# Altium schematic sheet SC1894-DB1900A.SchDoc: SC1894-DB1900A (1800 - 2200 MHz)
size B; Organization: Maxim Integrated; Address1: 160 Rio Robles; Address2: San Jose, CA. 95134; Address3: U.S.A.; Address4: 408-601-1000; Revision: 2.0; SheetNumber: 1; SheetTotal: 1; PageSetup: Record=PageOptions¦CenterHorizontal=True¦CenterVertical=True¦PrintScale=1.12¦XCorrection=1.00¦YCorrection=1.00¦PrintKind=1¦BorderSize=5000000¦LeftOffset=0¦BottomOffset=0¦Orientation=2¦PaperLength=1000¦PaperWidth=1000¦Scale=100¦PaperSource=15¦PrintQuality=600¦MediaType=1¦DitherType=10¦PaperKind=Tabloid¦PrintScaleMode=1
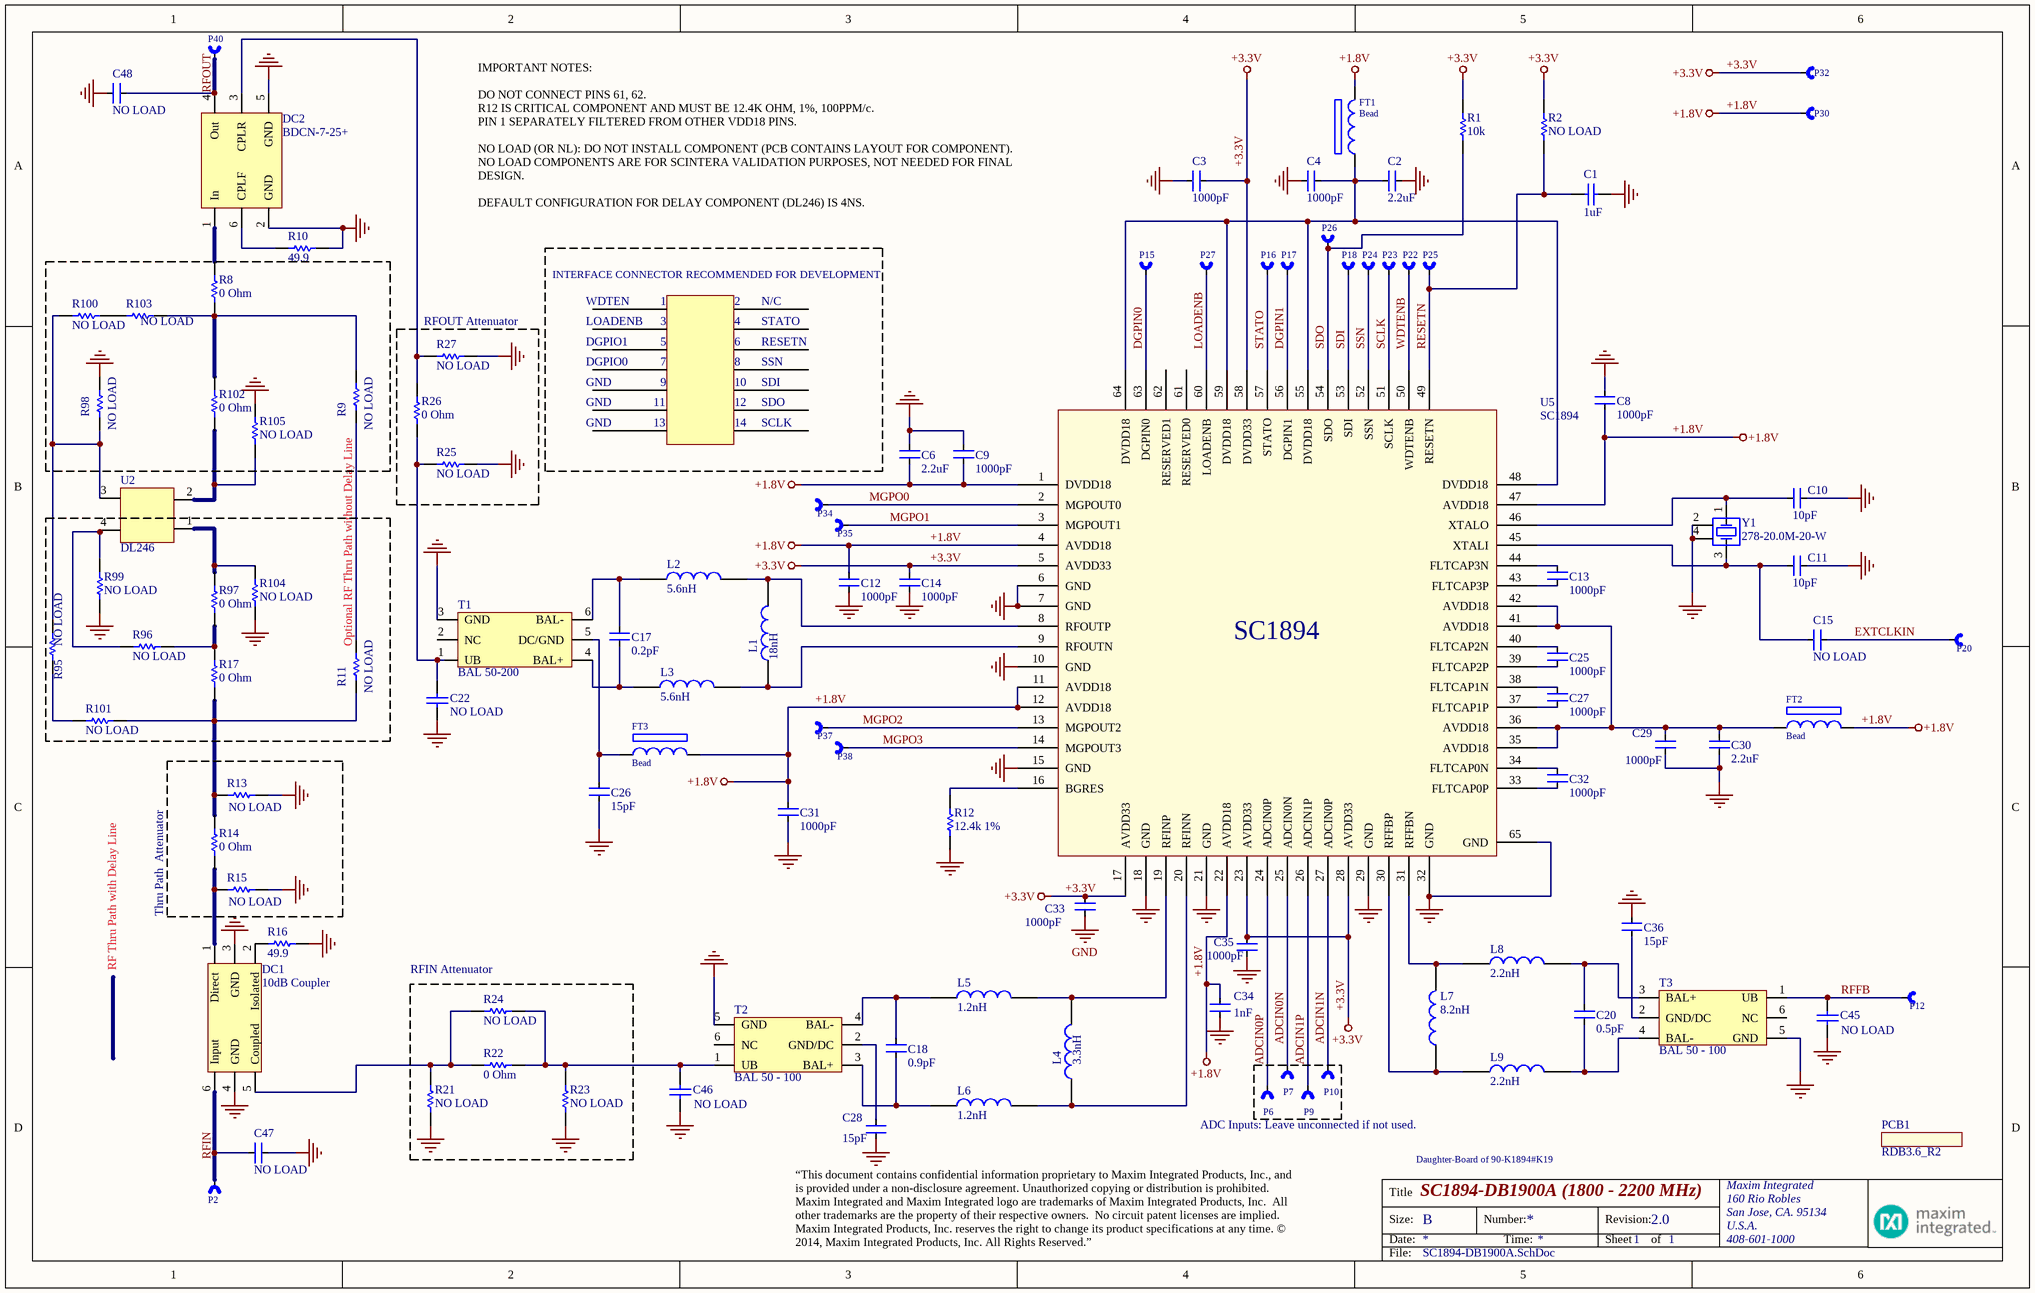
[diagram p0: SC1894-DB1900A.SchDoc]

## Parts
C1  1uF  [1608[0603]]
C2  2.2uF  [0603 SMD]
C3  1000pF  [0402 SMD]
C4  1000pF  [0402 SMD]
C6  2.2uF  [0603 SMD]
C8  1000pF  [0402 SMD]
C9  1000pF  [0402 SMD]
C10  10pF  [0402 SMD]
C11  10pF  [0402 SMD]
C12  1000pF  [0402 SMD]
C13  1000pF  [0402 SMD]
C14  1000pF  [0402 SMD]
C15  NO LOAD  [0402 SMD]
C17  0.2pF  [0402 SMD]
C18  0.9pF  [0402 SMD]
C20  0.5pF  [0402 SMD]
C22  NO LOAD  [0402 SMD]
C25  1000pF  [0402 SMD]
C26  15pF  [0402 SMD]
C27  1000pF  [0402 SMD]
C28  15pF  [0402 SMD]
C29  1000pF  [0402 SMD]
C30  2.2uF  [0603 SMD]
C31  1000pF  [0402 SMD]
C32  1000pF  [0402 SMD]
C33  1000pF  [0402 SMD]
C34  1nF  [0402 SMD]
C35  1000pF  [0402 SMD]
C36  15pF  [0402 SMD]
C45  NO LOAD  [0402 SMD]
C46  NO LOAD  [0402 SMD]
C47  NO LOAD  [0402 SMD]
C48  NO LOAD  [0402 SMD]
DC1  10dB Coupler  [0805 COUPLER ANAREN]
DC2  BDCN-7-25+  [BDCN-7-25+]
FT1  Bead  [0603 SMD]
FT2  Bead  [0603 SMD]
FT3  Bead  [0402 SMD]
L1  18nH  [0402 SMD]
L2  5.6nH  [0402 SMD]
L3  5.6nH  [0402 SMD]
L4  3.3nH  [0402 SMD]
L5  1.2nH  [0402 SMD]
L6  1.2nH  [0402 SMD]
L7  8.2nH  [0402 SMD]
L8  2.2nH  [0402 SMD]
L9  2.2nH  [0402 SMD]
P2  PORT 1-M  [PORT-1_M-PAD]  (value not drawn)
P6  PORT 1-M  [PORT-1_M-PAD]  (value not drawn)
P7  PORT 1-M  [PORT-1_M-PAD]  (value not drawn)
P9  PORT 1-M  [PORT-1_M-PAD]  (value not drawn)
P10  PORT 1-M  [PORT-1_M-PAD]  (value not drawn)
P12  PORT 1-M  [PORT-1_M-PAD]  (value not drawn)
P15  PORT 1-M  [PORT-1_M-PAD]  (value not drawn)
P16  PORT 1-M  [PORT-1_M-PAD]  (value not drawn)
P17  PORT 1-M  [PORT-1_M-PAD]  (value not drawn)
P18  PORT 1-M  [PORT-1_M-PAD]  (value not drawn)
P20  PORT 1-M  [PORT-1_M-PAD]  (value not drawn)
P22  PORT 1-M  [PORT-1_M-PAD]  (value not drawn)
P23  PORT 1-M  [PORT-1_M-PAD]  (value not drawn)
P24  PORT 1-M  [PORT-1_M-PAD]  (value not drawn)
P25  PORT 1-M  [PORT-1_M-PAD]  (value not drawn)
P26  PORT 1-M  [PORT-1_M-PAD]  (value not drawn)
P27  PORT 1-M  [PORT-1_M-PAD]  (value not drawn)
P30  PORT 1-M  [PORT-1_M-PAD]  (value not drawn)
P32  PORT 1-M  [PORT-1_M-PAD]  (value not drawn)
P34  PORT 1-M  [PORT-1_M-PAD]  (value not drawn)
P35  PORT 1-M  [PORT-1_M-PAD]  (value not drawn)
P37  PORT 1-M  [PORT-1_M-PAD]  (value not drawn)
P38  PORT 1-M  [PORT-1_M-PAD]  (value not drawn)
P40  PORT 1-M  [PORT-1_M-PAD]  (value not drawn)
PCB1  RDB3.6_R2
R1  10k  [0402 SMD]
R2  NO LOAD  [0402 SMD]
R8  0 Ohm  [0402 SMD]
R9  NO LOAD  [0402 SMD]
R10  49.9  [0402 SMD]
R11  NO LOAD  [0402 SMD]
R12  12.4k 1%  [0402 SMD]
R13  NO LOAD  [0402 SMD]
R14  0 Ohm  [0402 SMD]
R15  NO LOAD  [0402 SMD]
R16  49.9  [0402 SMD]
R17  0 Ohm  [0402 SMD]
R21  NO LOAD  [0402 SMD]
R22  0 Ohm  [0201_SMT]
R23  NO LOAD  [0402 SMD]
R24  NO LOAD  [0201_SMT]
R25  NO LOAD  [0402 SMD]
R26  0 Ohm  [0402 SMD]
R27  NO LOAD  [0402 SMD]
R95  NO LOAD  [0402 SMD]
R96  NO LOAD  [0402 SMD]
R97  0 Ohm  [0402 SMD]
R98  NO LOAD  [0402 SMD]
R99  NO LOAD  [0402 SMD]
R100  NO LOAD  [0402 SMD]
R101  NO LOAD  [0402 SMD]
R102  0 Ohm  [0402 SMD]
R103  NO LOAD  [0402 SMD]
R104  NO LOAD  [0402 SMD]
R105  NO LOAD  [0402 SMD]
T1  BAL 50-200
T2  BAL 50 - 100  [0805 BALUN Anaren]
T3  BAL 50 - 100  [0805 BALUN Anaren]
U2  DL246  [DL246-A]
U5  SC1894  [SC1894]
Y1  278-20.0M-20-W  [278-20.0M]

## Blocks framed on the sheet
RFOUT Attenuator: R25-R27
Optional RF Thru Path without Delay Line: R11 R17 R95-R97 R99 R101 R104
Thru Path  Attenuator: R13-R15
RFIN Attenuator: R21-R24

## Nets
+1.8V: C6.2 C8.2 C9.2 C12.1 C31.2 C34.2 FT1.2 FT2.2 FT3.2 P30.1(P*) U5.1(DVDD18) U5.4(AVDD18) U5.11(AVDD18) U5.12(AVDD18) U5.22(AVDD18) U5.47(AVDD18)
+3.3V: C3.2 C14.1 C33.1 C35.2 P32.1(P*) R1.1 R2.2 U5.5(AVDD33) U5.17(AVDD33) U5.23(AVDD33) U5.28(AVDD33) U5.58(DVDD33)
GND: C1.1 C2.2 C3.1 C4.1 C6.1 C8.1 C9.1 C10.2 C11.2 C12.2 C14.2 C22.1 C26.2 C28.2 C29.2 C30.2 C31.1 C33.2 C34.1 C35.1 C36.2 C45.1 C46.1 C47.2 C48.1 DC1.3(GND) DC1.4(GND) DC2.2(GND) DC2.5(GND) R10.2 R12.2 R13.2 R15.2 R16.2 R21.2 R23.2 R25.1 R27.1 R98.1 R99.1 R104.1 R105.2 T1.3(GND) T2.5(GND) T3.5(GND) U5.6(GND) U5.7(GND) U5.10(GND) U5.15(GND) U5.18(GND) U5.21(GND) U5.29(GND) U5.32(GND) U5.65(GND) Y1.2(SHIELD1) Y1.4(SHIELD2)
ADCIN0N: P7.1(P*) U5.25(ADCIN0N)
ADCIN0P: P6.1(P*) U5.24(ADCIN0P)
ADCIN1N: P10.1(P*) U5.27(ADCIN0P)
ADCIN1P: P9.1(P*) U5.26(ADCIN1P)
DGPIN0: P15.1(P*) U5.63(DGPIN0)
DGPIN1: P17.1(P*) U5.56(DGPIN1)
EXTCLKIN: C15.2 P20.1(P*)
LOADENB: P27.1(P*) U5.60(LOADENB)
MGPO0: P34.1(P*) U5.2(MGPOUT0)
MGPO1: P35.1(P*) U5.3(MGPOUT1)
MGPO2: P37.1(P*) U5.13(MGPOUT2)
MGPO3: P38.1(P*) U5.14(MGPOUT3)
RESETN: C1.2 P25.1(P*) R2.1 U5.49(RESETN)
RFFB: C45.2 P12.1(P*) T3.1(UB)
RFIN: C47.1 DC1.6(Input) P2.1(P*)
RFOUT: C48.2 DC2.4(Out) P40.1(P*)
SCLK: P23.1(P*) U5.51(SCLK)
SDI: P18.1(P*) U5.53(SDI)
SDO: P26.1(P*) R1.2 U5.54(SDO)
SSN: P24.1(P*) U5.52(SSN)
STATO: P16.1(P*) U5.57(STATO)
WDTENB: P22.1(P*) U5.50(WDTENB)
NetC2_1: C2.1 C4.2 FT1.1 U5.48(DVDD18) U5.55(DVDD18) U5.59(DVDD18) U5.64(DVDD18)
NetC10_1: C10.1 U5.46(XTALO) Y1.1(OSC1)
NetC11_1: C11.1 C15.1 U5.45(XTALI) Y1.3(OSC2)
NetC13_1: C13.1 U5.44(FLTCAP3N)
NetC13_2: C13.2 U5.43(FLTCAP3P)
NetC17_1: C17.1 L2.1 T1.6(BAL-)
NetC17_2: C17.2 L3.1 T1.4(BAL+)
NetC18_1: C18.1 L5.1 T2.4(BAL-)
NetC18_2: C18.2 L6.1 T2.3(BAL+)
NetC20_1: C20.1 L8.2 T3.3(BAL+)
NetC20_2: C20.2 L9.2 T3.4(BAL-)
NetC22_2: C22.2 R25.2 R26.1 T1.1(UB)
NetC25_1: C25.1 U5.40(FLTCAP2N)
NetC25_2: C25.2 U5.39(FLTCAP2P)
NetC26_1: C26.1 FT3.1 T1.5(DC/GND)
NetC27_1: C27.1 U5.38(FLTCAP1N)
NetC27_2: C27.2 U5.37(FLTCAP1P)
NetC28_1: C28.1 T2.2(GND/DC)
NetC29_1: C29.1 C30.1 FT2.1 U5.35(AVDD18) U5.36(AVDD18) U5.41(AVDD18) U5.42(AVDD18)
NetC32_1: C32.1 U5.34(FLTCAP0N)
NetC32_2: C32.2 U5.33(FLTCAP0P)
NetC36_1: C36.1 T3.2(GND/DC)
NetC46_2: C46.2 R22.2 R23.1 R24.2 T2.1(UB)
NetDC1_1: DC1.1(Direct) R14.1 R15.1
NetDC1_2: DC1.2(Isolated) R16.1
NetDC1_5: DC1.5(Coupled) R21.1 R22.1 R24.1
NetDC2_1: DC2.1(In) R8.2
NetDC2_3: DC2.3(CPLR) R26.2 R27.2
NetDC2_6: DC2.6(CPLF) R10.1
NetL1_1: L1.1 L3.2 U5.9(RFOUTN)
NetL1_2: L1.2 L2.2 U5.8(RFOUTP)
NetL4_1: L4.1 L6.2 U5.20(RFINN)
NetL4_2: L4.2 L5.2 U5.19(RFINP)
NetL7_1: L7.1 L9.1 U5.30(RFFBP)
NetL7_2: L7.2 L8.1 U5.31(RFFBN)
NetR8_1: R8.1 R9.2 R102.2 R103.2
NetR9_1: R9.1 R11.2
NetR11_1: R11.1 R13.1 R14.2 R17.1 R101.2
NetR12_1: R12.1 U5.16(BGRES)
NetR17_2: R17.2 R96.2 R97.1
NetR95_1: R95.1 R101.1
NetR95_2: R95.2 R98.2 R100.1 U2.3(2ns_B)
NetR96_1: R96.1 R99.2 U2.4(2ns_A)
NetR97_2: R97.2 R104.2 U2.1(4ns_A)
NetR100_2: R100.2 R103.1
NetR102_1: R102.1 R105.1 U2.2(4ns_B)

Not connected (* = marked no-connect by the designer): T1 2(NC); T2 6(NC); T3 6(NC); U5 61(RESERVED0) 62(RESERVED1)

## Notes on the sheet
- IMPORTANT NOTES:
  DO NOT CONNECT PINS 61, 62.
  R12 IS CRITICAL COMPONENT AND MUST BE 12.4K OHM, 1%, 100PPM/c.
  PIN 1 SEPARATELY FILTERED FROM OTHER VDD18 PINS.
  NO LOAD (OR NL): DO NOT INSTALL COMPONENT (PCB CONTAINS LAYOUT FOR COMPONENT).
  NO LOAD COMPONENTS ARE FOR SCINTERA VALIDATION PURPOSES, NOT NEEDED FOR FINAL DESIGN.
  DEFAULT CONFIGURATION FOR DELAY COMPONENT (DL246) IS 4NS.
- INTERFACE CONNECTOR RECOMMENDED FOR DEVELOPMENT
- WDTEN
- LOADENB
- DGPIO1
- DGPIO0
- 1
- 3
- 5
- 7
- 2
- 4
- 6
- 8
- N/C
- STATO
- RESETN
- SSN
- GND
- 11
- 13
- 9
- 10
- 12
- 14
- SDI
- SDO
- SCLK
- RF Thru Path with Delay Line
- ADC Inputs: Leave unconnected if not used.
- Daughter-Board of 90-K1894#K19
- (near C28) “This document contains confidential information proprietary to Maxim Integrated Products, Inc., and is provided under a non-disclosure agreement. Unauthorized copying or distribution is prohibited.  Maxim Integrated and Maxim Integrated logo are trademarks of Maxim Integrated Products, Inc.  All other trademarks are the property of their respective owners.  No circuit patent licenses are implied.  Maxim Integrated Products, Inc. reserves the right to change its product specifications at any time. © 2014, Maxim Integrated Products, Inc. All Rights Reserved.”

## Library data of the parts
C1 = 1u: 1uF 0603 ceramic capacitor
C2 C6 C30 = Cap 2.2uF 0603: 2.2uF 0603
C3 C4 C8 C9 C12-C14 C25 C27 C29 C31-C35 = Cap 1000pF: 1000pF 0402
C10 C11 C15 = Cap 10pF: 10pF 0402
C17 = Cap 0.2pF: 0.2pF 0402; Part Substitution Allowed?: No
C18 = Cap 0.9pF: 0.9pF 0402; Part Substitution Allowed?: No
C20 = Cap 0.5pF: 0.5pF 0402; Part Substitution Allowed?: No
C22 C45 C46 = Capacitor: Generic Capacitor
C26 C28 C36 = Cap 15pF: 15pF 0402
C47 C48 = Cap No Load 0402: 0402 Cap No Load
DC1 = DC1722J5010AHF: Anaren 1700 - 2200 MHz 0805 10dB Coupler; Part Substitution Allowed?: No
DC2 = BDCN-7-25+: Mini Circuits Balun; Manufacturer 1: Mini-Circuits; Part Substitution Allowed?: No
FT1 FT2 = Bead 0603: Part Substitution Allowed?: No; Value: 120mH
FT3 = Bead 0402: Bead 0402 470 ohm; Part Substitution Allowed?: No; Value: 470mH
L1 = 18nH: Part Substitution Allowed?: No
L2 L3 = 5.6nH: Part Substitution Allowed?: No
L5 L6 = 1.2nH: Part Substitution Allowed?: No
L7 = 8.2nH: Part Substitution Allowed?: No
L8 L9 = 2.2nH: Part Substitution Allowed?: No
P2 P6 P7 P9 P10 P12 P15-P18 P20 P22-P27 P30 P32 P34 P35 P37 P38 P40 = PORT 1-M: Ports of RDB Daughterboards
PCB1 = RDB3.6_R2: Printed Circuit Board (RDB3.6_R2)
R1 = 10k Ohm 0402
R2 R21 R23 R95 R96 R99-R101 R103-R105 = RES NL 0402: NO LOAD RESISTOR 0402
R8 R14 R17 R26 R97 R102 = 0 Ohm 0402
R9 R11 R13 R15 R25 R27 R98 = Resistor: Resistor Generic
R10 R16 = 49.9 Ohm: 40 Ohm 0402
R12 = 12.4k Ohm 0402
R22 = 0 Ohm 0201
R24 = RES NL 0201: NO LOAD RESISTOR 0201
T1 = DXP18BN5014T
T2 T3 = BD1722J50100A00: Anaren 1700 - 2200 MHz 50Ohm UnBal - 100 Dif Balun; Part Substitution Allowed?: No
U2 = DL246: Kyocera Delay Line DL246; Part Substitution Allowed?: No
U5 = SC1894: SC1894: Adaptive RF Power Amplifier Linearizer; Manufacturer 1: Scintera; Manufacturer Part Number 1: SC1894A-00A00
Y1 = 278-20.0M-20-W: Crystal 20MHz 278-20.0M-20-W; Manufacturer 1: Oscilent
